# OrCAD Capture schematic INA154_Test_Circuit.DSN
size A; title: INA154 High-Speed, Precision DIFFERENCE AMPLIFIER(G=1); rev: 1.1; note: Datasheet: SBOS104  EVM: N/A
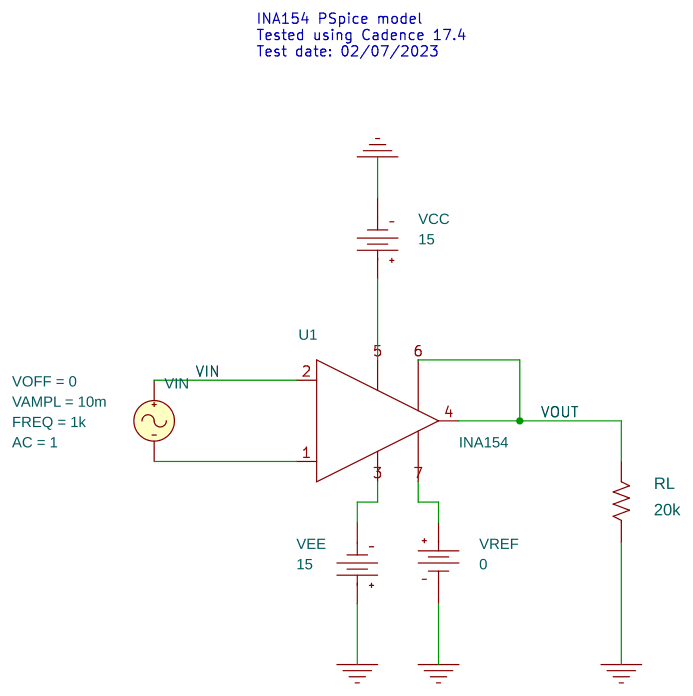
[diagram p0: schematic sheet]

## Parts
RL  20k  [AX/RC05]
U1  INA154
VCC  VDC
VEE  VDC
VIN  VSIN
VREF  VDC

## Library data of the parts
RL = R
U1 = INA154
VCC VEE = VDC: DC: 15
VIN = VSIN: AC: 1; FREQ: 1k; VAMPL: 10m; VOFF: 0
VREF = VDC: DC: 0

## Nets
VIN: U1.2(-) VIN.1(+)
0: RL.1 VCC.1(-) VEE.0(+) VREF.1(-)
VOUT: RL.2 U1.4(OUT) U1.6(SENSE)
N14298623: U1.1(+) VIN.2(-)
N14298647: U1.3(V-) VEE.1(-)
N14298653: U1.7(REF) VREF.0(+)
N14298948: U1.5(V+) VCC.0(+)

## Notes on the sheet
- INA154 PSpice model
  Tested using Cadence 17.4
  Test date: 02/07/2023
